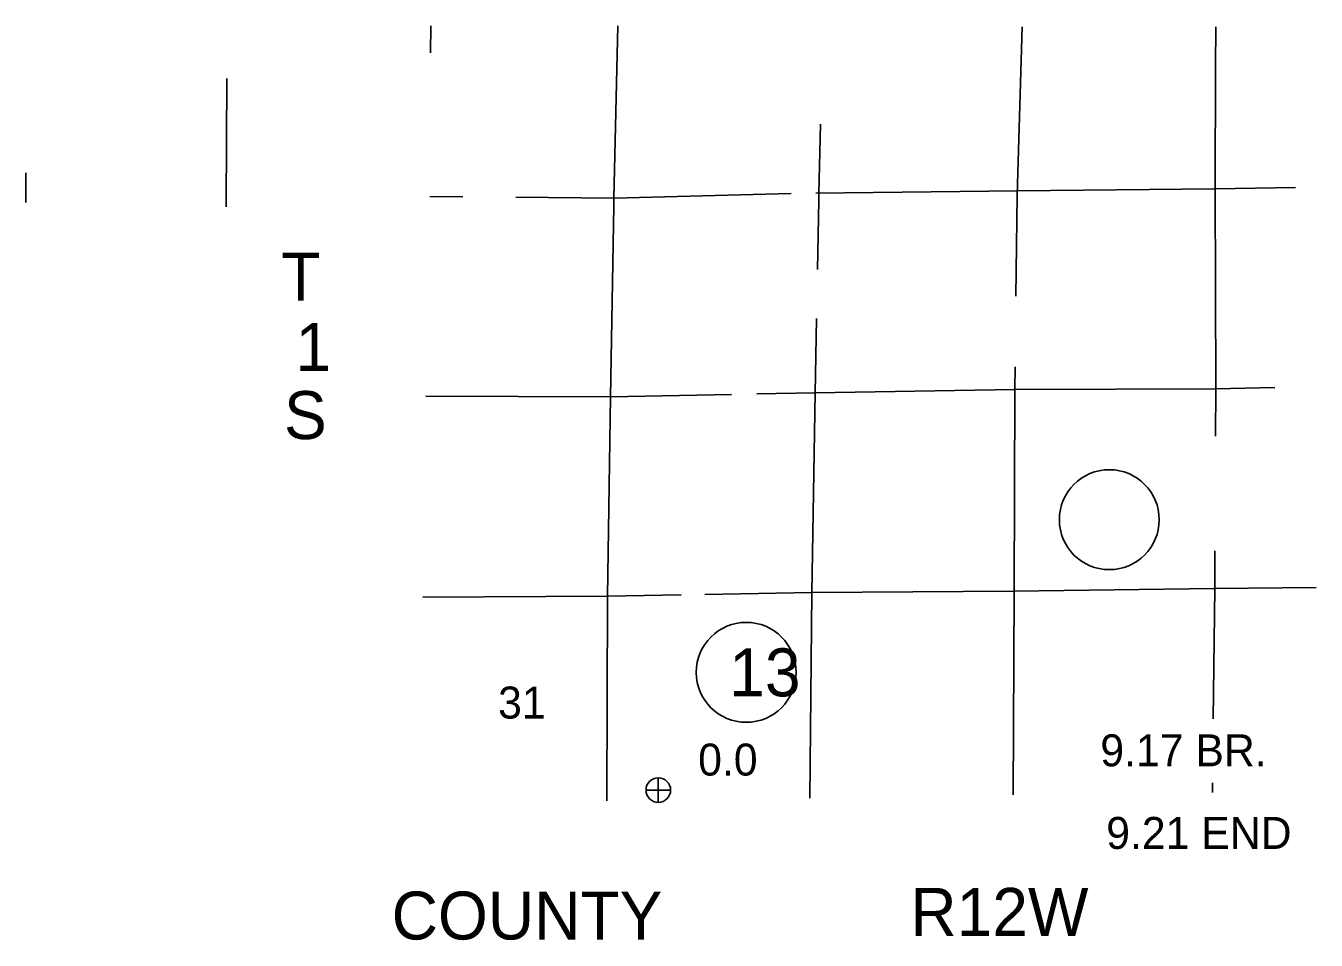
# Model space of a CAD drawing. Extents: x 1127717 to 1741049, y 2026793 to 2244711.
# Drawn here: x 1160984 to 1169507, y 2111668 to 2117709 of the extents above; entities that cross this region are included whole.
import ezdxf

# ---------------------------------------------------------------- set-up
doc = ezdxf.new("R2010")
doc.units = 0
for name, color, linetype in [('25', 7, 'Continuous'), ('26', 7, 'Continuous'), ('27', 7, 'Continuous'), ('30', 7, 'Continuous'), ('4', 7, 'Continuous'), ('5', 7, 'Continuous'), ('58', 7, 'Continuous')]:
    doc.layers.add(name, color=color, linetype=linetype)

msp = doc.modelspace()

# ---------------------------------------------------------------- linework, layer by layer
at = {"layer": '26'}
for p, q in [((1165161.6, 2112578.6), (1165161.6, 2112741.1)), ((1165080.4, 2112659.8), (1165242.9, 2112659.8))]:
    msp.add_line(p, q, dxfattribs=at)
msp.add_circle((1165161.6, 2112659.8), 81.2, dxfattribs=at)
at = {"layer": '27'}
for centre in [(1168140.7, 2114446.2), (1165742.4, 2113437.6)]:
    msp.add_circle(centre, 330, dxfattribs=at)
at = {"layer": '4'}
msp.add_lwpolyline([(1163658.8, 2117708.8), (1163657.7, 2117530.1)], dxfattribs=at)
at = {"layer": '5'}
for points in [[(1164894.2, 2117708.7), (1164868.4, 2116570.2), (1164868.5, 2116518.6)], [(1167564.3, 2117702.4), (1167532.6, 2116590.3)], [(1168843.9, 2117702.4), (1168842.8, 2117439.7)], [(1168842.8, 2117439.7), (1168839.5, 2116632.4)], [(1162312.6, 2117361.3), (1162308, 2116528.3), (1162307.8, 2116513)], [(1166233.1, 2117059.3), (1166221.3, 2116600.2), (1166221.3, 2116555.2)], [(1160984.7, 2116736.5), (1160983.6, 2116541.6)], [(1166203.1, 2116603.5), (1167534, 2116617.9), (1168839.5, 2116632.4)], [(1168839.5, 2116632.4), (1169371.3, 2116640)], [(1168839.5, 2116632.4), (1168844.2, 2115310.1), (1168842.5, 2114997.9)], [(1163652, 2116580.3), (1163870.5, 2116578.7)], [(1164220.2, 2116576.1), (1164869.4, 2116571.2), (1166039.8, 2116600.5)], [(1166221.3, 2116555.2), (1166213, 2116099.6)], [(1167532.6, 2116590.3), (1167524.2, 2115923.7)], [(1164868.5, 2116518.6), (1164845.5, 2115257.6), (1164826.2, 2113938.9), (1164822.4, 2112589.2)], [(1166207.1, 2115776.1), (1166198.2, 2115282.8), (1166176.4, 2113963.5), (1166162.8, 2112606.7)], [(1167518.3, 2115455.8), (1167516.4, 2115306.6), (1167512, 2113972.7), (1167505.8, 2112627.6)], [(1163625.6, 2115263.1), (1164845.5, 2115257.1), (1165644.3, 2115273.5)], [(1165813.3, 2115276.9), (1166197.6, 2115284.8), (1167516.9, 2115307.1), (1168844.2, 2115310.1), (1169233.7, 2115318.4)], [(1168838.3, 2114241.5), (1168836.9, 2113990.7), (1168827.5, 2113129.5)], [(1169507.4, 2113998.4), (1168834.9, 2113990.6), (1167511, 2113973.7), (1166175.9, 2113965), (1165469.2, 2113952.4)], [(1165311.7, 2113949.5), (1164823.7, 2113940.8), (1163605.6, 2113933.3)], [(1168822.9, 2112708.4), (1168822.2, 2112643.2)]]:
    msp.add_lwpolyline(points, dxfattribs=at)

# ---------------------------------------------------------------- texts
at = {"layer": '25'}
for s, p in [('0.0', (1165424.9, 2112755.8)), ('9.21 END', (1168120.3, 2112271.2))]:
    msp.add_text(s, height=211.2, dxfattribs=at).set_placement(p)
at = {"layer": '27'}
msp.add_text('13', height=316.8, dxfattribs=at).set_placement((1165630.2, 2113279.2))
at = {"layer": '30'}
for s, p in [('T', (1162671, 2115893.8)), ('1', (1162765.8, 2115429.2)), ('S', (1162689, 2114978.8)), ('COUNTY', (1163400.1, 2111672.8)), ('R12W', (1166826.3, 2111696.7))]:
    msp.add_text(s, height=316.8, dxfattribs=at).set_placement(p)
at = {"layer": '5'}
msp.add_text('31', height=211.2, dxfattribs=at).set_placement((1164103.4, 2113132.5))
at = {"layer": '58'}
msp.add_text('9.17 BR.', height=211.2, dxfattribs=at).set_placement((1168081.3, 2112817))

doc.saveas('drawing.dxf')
